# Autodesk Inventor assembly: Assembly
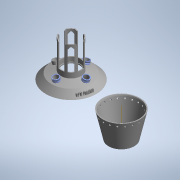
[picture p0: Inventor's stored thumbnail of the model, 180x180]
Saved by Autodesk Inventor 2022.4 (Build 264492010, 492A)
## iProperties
Part Number: Assembly
Document SubType Name: Assembly
Designer: tmass
Author: tmass
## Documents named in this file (3)
- C:\Users\tmass\OneDrive\Bureau\UFO paper\3D models\UFO\Inventor\Assembly.iam
- C:\Users\tmass\OneDrive\Bureau\UFO paper\3D models\UFO\Inventor\Box.ipt
- C:\Users\tmass\OneDrive\Bureau\UFO paper\3D models\UFO\Inventor\Top cover 4 vials.ipt
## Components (2 placed, 2 different names)
1. Box:1
2. Top cover 4 vials:1
